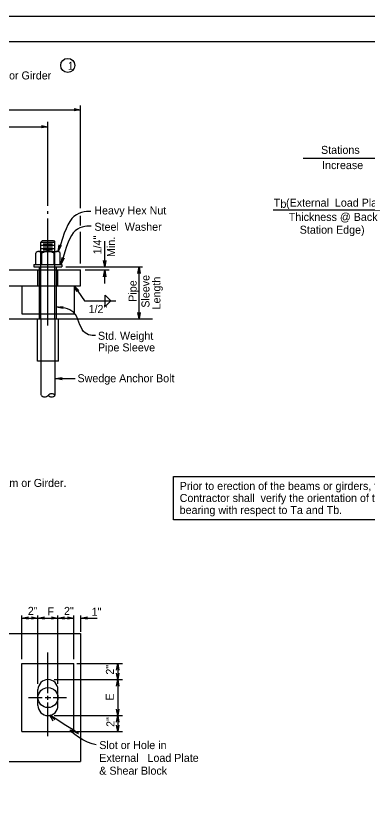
# Model space of a CAD drawing. Extents: x 113 to 232, y -103 to -27.
# Drawn here: x 181.6 to 185.26, y -54.65 to -46.32 of the extents above; entities that cross this region are included whole.
import ezdxf

# ---------------------------------------------------------------- set-up
doc = ezdxf.new("R2010")
doc.units = 0
for name, color, linetype in [('1', 7, 'Continuous'), ('B_Border', 7, 'Continuous'), ('B_Dimension', 7, 'Continuous'), ('B_No_Plot', 7, 'Continuous')]:
    doc.layers.add(name, color=color, linetype=linetype)

msp = doc.modelspace()

# ---------------------------------------------------------------- linework, layer by layer
at = {"layer": '1'}
for p, q in [((182.2718, -48.3172), (182.2718, -47.2475)), ((179.1359, -47.2922), (182.2718, -47.2922)), ((181.9318, -48.2933), (181.9318, -47.419)), ((180.706, -47.469), (181.9318, -47.469)), ((184.5891, -47.7957), (185.647, -47.7957)), ((181.9318, -48.3756), (181.9318, -48.3482)), ((184.2742, -48.333), (185.6721, -48.333)), ((181.9318, -49.5368), (181.9318, -48.4227)), ((182.2718, -48.4956), (182.2718, -48.3959)), ((182.2718, -48.8924), (182.2718, -48.5639)), ((181.8589, -48.6707), (181.8752, -48.6543)), ((181.8589, -48.6707), (182.0047, -48.6707)), ((181.8589, -48.7678), (181.8589, -48.6707)), ((181.8589, -48.6707), (182.0047, -48.6707)), ((181.8752, -48.6543), (181.9884, -48.6543)), ((181.8832, -48.687), (181.9804, -48.687)), ((181.9884, -48.6543), (182.0047, -48.6707)), ((182.0047, -48.7678), (182.0047, -48.6707)), ((182.5231, -48.9288), (182.5231, -48.6599)), ((181.8365, -48.7678), (182.0273, -48.7678)), ((181.8589, -48.7031), (182.0047, -48.7031)), ((181.8589, -48.7354), (182.0047, -48.7354)), ((181.8589, -49.4703), (181.8589, -48.7678)), ((181.8832, -48.7194), (181.9804, -48.7194)), ((181.8832, -48.7518), (181.9804, -48.7518)), ((182.0047, -49.4703), (182.0047, -48.7678)), ((181.8045, -48.9017), (181.8045, -48.7862)), ((181.8688, -48.9017), (181.8688, -48.7862)), ((181.995, -48.9017), (181.995, -48.7862)), ((182.0595, -48.9017), (182.0595, -48.7862)), ((181.786, -48.9017), (182.0776, -48.9017)), ((181.786, -48.9017), (181.786, -48.9277)), ((181.786, -48.9277), (182.0776, -48.9277)), ((181.8433, -48.9606), (181.8433, -48.9273)), ((182.0203, -48.9606), (182.0203, -48.9283)), ((182.0776, -48.9017), (182.0776, -48.9277)), ((182.1175, -48.9277), (182.9164, -48.9277)), ((182.8804, -49.4703), (182.8804, -48.9277)), ((179.1359, -48.9598), (182.2718, -48.9598)), ((181.8277, -49.1273), (181.8277, -48.9606)), ((181.8433, -49.1273), (181.8433, -48.9606)), ((182.0203, -49.1283), (182.0203, -48.9636)), ((182.0359, -49.1283), (182.0359, -48.9636)), ((182.2718, -49.1264), (182.2718, -48.9598)), ((182.3196, -48.9598), (182.5687, -48.9598)), ((182.5231, -49.0998), (182.5231, -48.9622)), ((179.1359, -49.1264), (182.2718, -49.1264)), ((181.661, -49.1264), (181.661, -49.4181)), ((181.8433, -49.4181), (181.8433, -49.1273)), ((182.0203, -49.4181), (182.0203, -49.1283)), ((182.2026, -49.1264), (182.2026, -49.4181)), ((182.2026, -49.1264), (182.3126, -49.2823)), ((182.5267, -49.3413), (182.5267, -49.2233)), ((182.5267, -49.2233), (182.5857, -49.2823)), ((182.3126, -49.2823), (182.639, -49.2823)), ((182.5857, -49.2823), (182.5267, -49.3413)), ((181.661, -49.4181), (182.2027, -49.4181)), ((181.8433, -49.4703), (181.8433, -49.4181)), ((182.0203, -49.4703), (182.0203, -49.4181)), ((178.3401, -49.4703), (183.0184, -49.4703)), ((181.8233, -49.9105), (181.8233, -49.4703)), ((181.8589, -49.4703), (181.8589, -49.9105)), ((182.0047, -49.4703), (182.0047, -49.9105)), ((182.0403, -49.9105), (182.0403, -49.4703)), ((182.0403, -49.9105), (181.8233, -49.9105)), ((181.8589, -49.9105), (181.8589, -50.2636)), ((182.0047, -49.9105), (182.0047, -50.2638)), ((182.0116, -50.0903), (182.2143, -50.0903)), ((181.6609, -53.011), (181.6609, -52.5571)), ((181.6609, -52.5832), (181.8276, -52.5832)), ((181.8276, -53.2697), (181.8276, -52.5571)), ((181.8276, -52.5832), (182.0359, -52.5832)), ((182.0359, -53.2697), (182.0359, -52.5571)), ((182.0359, -52.5832), (182.2025, -52.5832)), ((182.2025, -53.011), (182.2025, -52.5571)), ((182.2735, -52.7253), (182.2735, -52.5571)), ((182.2735, -52.5832), (182.4434, -52.5832)), ((181.3298, -52.7449), (182.2718, -52.7449)), ((182.2718, -52.7449), (182.2718, -54.0782)), ((181.9317, -53.3636), (181.9317, -52.9409)), ((181.6609, -53.0574), (182.2025, -53.0574)), ((181.6609, -53.7658), (181.6609, -53.0574)), ((182.2025, -53.7658), (182.2025, -53.0574)), ((182.2332, -53.0574), (182.709, -53.0574)), ((182.6581, -53.0574), (182.6581, -53.2241)), ((181.9955, -53.2241), (182.709, -53.2241)), ((182.6581, -53.2241), (182.6581, -53.5991)), ((181.8276, -53.4949), (181.8276, -53.3282)), ((182.0359, -53.4949), (182.0359, -53.3282)), ((181.728, -53.4116), (181.8722, -53.4116)), ((181.9034, -53.4116), (181.9626, -53.4116)), ((181.9317, -53.4331), (181.9317, -53.3914)), ((181.9869, -53.4116), (182.0359, -53.4116)), ((182.0359, -53.4116), (182.1258, -53.4116)), ((181.9317, -53.8125), (181.9317, -53.4626)), ((181.9955, -53.5991), (182.709, -53.5991)), ((182.6581, -53.5991), (182.6581, -53.7658)), ((181.6609, -53.7658), (182.2025, -53.7658)), ((182.2332, -53.7658), (182.709, -53.7658)), ((181.3263, -54.0782), (182.2718, -54.0782))]:
    msp.add_line(p, q, dxfattribs=at)
for points in [[(181.8252, -48.9598), (181.8252, -48.9598)], [(182.2322, -49.1893), (182.2026, -49.1264), (182.2518, -49.1753)]]:
    msp.add_lwpolyline(points, dxfattribs=at)
msp.add_lwpolyline([(183.2378, -51.111), (186.1787, -51.111), (186.1787, -51.5619), (183.2378, -51.5619)], close=True, dxfattribs=at)
for centre, radius in [((182.1373, -46.8307), 0.0733), ((181.9318, -53.4116), 0.1042)]:
    msp.add_circle(centre, radius, dxfattribs=at)
for centre, radius, start, end in [((181.8366, -48.8053), 0.0375, 30.80861, 149.1914), ((181.9319, -48.8859), 0.118, 57.68982, 122.31018), ((182.0273, -48.8055), 0.0376, 30.95728, 149.04272), ((181.8969, -50.2305), 0.0504, 223.71346, 316.28654), ((181.9698, -50.3002), 0.0504, 43.71346, 136.28654), ((181.9698, -50.2305), 0.0504, 223.71346, 316.28654), ((181.9318, -53.3282), 0.1042, 0, 180), ((181.9318, -53.4949), 0.1042, 180, 0)]:
    msp.add_arc(centre, radius, start, end, dxfattribs=at)
for points in [[(182.3767, -48.3506), (182.36, -48.35), (182.1729, -48.347), (182.102, -48.5671), (182.0375, -48.7678)], [(182.3799, -48.5045), (182.3635, -48.5039), (182.1862, -48.4973), (182.1251, -48.7063), (182.0707, -48.898)], [(182.4272, -49.6424), (182.4104, -49.6436), (182.2728, -49.6497), (182.2378, -49.3572), (182.0673, -49.3499), (182.0221, -49.3479)], [(182.4347, -53.9018), (182.3268, -53.8988), (181.9515, -53.5952), (182.4347, -53.9018), (181.9515, -53.5952)]]:
    msp.add_open_spline(points, degree=3, dxfattribs=at)
at = {"layer": 'B_Border'}
msp.add_line((177.6403, -46.5803), (198.7169, -46.5803), dxfattribs=at)
at = {"layer": 'B_Dimension'}
for points in [[(182.2035, -47.2802), (182.2718, -47.2922), (182.2035, -47.3043)], [(181.8635, -47.4569), (181.9318, -47.469), (181.8635, -47.481)], [(182.0699, -48.7065), (182.0375, -48.7678), (182.0469, -48.6991)], [(182.1009, -48.8355), (182.0707, -48.898), (182.0778, -48.829)], [(182.5352, -48.8605), (182.5231, -48.9288), (182.5111, -48.8605)], [(182.8684, -48.996), (182.8804, -48.9277), (182.8924, -48.996)], [(182.5111, -49.0305), (182.5231, -48.9622), (182.5352, -49.0305)], [(182.0899, -49.3629), (182.0221, -49.3479), (182.0909, -49.3388)], [(182.8924, -49.4019), (182.8804, -49.4703), (182.8684, -49.4019)], [(182.0799, -50.1023), (182.0116, -50.0903), (182.0799, -50.0782)], [(181.7292, -52.5953), (181.6609, -52.5832), (181.7292, -52.5712)], [(181.7592, -52.5712), (181.8276, -52.5832), (181.7592, -52.5953)], [(181.7592, -52.5712), (181.8276, -52.5832), (181.7592, -52.5953)], [(181.7592, -52.5712), (181.8276, -52.5832), (181.7592, -52.5953)], [(181.8959, -52.5953), (181.8276, -52.5832), (181.8959, -52.5712)], [(181.9676, -52.5712), (182.0359, -52.5832), (181.9676, -52.5953)], [(182.1042, -52.5953), (182.0359, -52.5832), (182.1042, -52.5712)], [(182.1342, -52.5712), (182.2025, -52.5832), (182.1342, -52.5953)], [(182.3418, -52.5953), (182.2735, -52.5832), (182.3418, -52.5712)], [(182.646, -53.1257), (182.6581, -53.0574), (182.6701, -53.1257)], [(182.6701, -53.1557), (182.6581, -53.2241), (182.646, -53.1557)], [(182.646, -53.2924), (182.6581, -53.2241), (182.6701, -53.2924)], [(181.9843, -53.6564), (181.9515, -53.5952), (182.0032, -53.6415)], [(182.6701, -53.5307), (182.6581, -53.5991), (182.646, -53.5307)], [(182.646, -53.6674), (182.6581, -53.5991), (182.6701, -53.6674)], [(182.6701, -53.6974), (182.6581, -53.7658), (182.646, -53.6974)]]:
    msp.add_lwpolyline(points, dxfattribs=at)
at = {"layer": 'B_No_Plot'}
msp.add_lwpolyline([(176.6886, -46.3166), (199.0219, -46.3166), (199.0219, -60.5406), (176.6886, -60.5406)], close=True, dxfattribs=at)

# ---------------------------------------------------------------- texts
at = {"layer": '1'}
for s, height, p in [('1', 0.0833, (182.1381, -46.8763)), ('C.L. Beam or Girder', 0.083334, (180.969, -46.9769)), ('Stations', 0.08333, (184.7738, -47.7518)), ('Increase', 0.08333, (184.7853, -47.9102)), ('T  (External  Load Plate', 0.083334, (184.2803, -48.3012)), ('b', 0.0833, (184.3512, -48.3133)), ('Heavy Hex Nut', 0.083334, (182.4138, -48.3821)), ('Thickness @ Back', 0.083334, (184.4378, -48.4496)), ('Steel  Washer', 0.083334, (182.4154, -48.5521)), ('Station Edge)', 0.083334, (184.5521, -48.5829)), ('1/2"', 0.08333, (182.3546, -49.4084)), ('Std. Weight ', 0.083334, (182.452, -49.6869)), ('Pipe Sleeve', 0.083334, (182.452, -49.8078)), ('Swedge Anchor Bolt', 0.083334, (182.2389, -50.1289)), ('C.L Elastomeric Pad shal l  be aligned with C.L. Beam or Girder.', 0.083334, (178.9532, -51.2186)), ('Prior to erection of the beams or girders, the ', 0.083334, (183.3027, -51.2501)), ('Contractor shall  verify the orientation of the ', 0.083334, (183.3027, -51.3751)), ('bearing with respect to Ta and Tb.', 0.083334, (183.3027, -51.5001)), ('2"', 0.08333, (181.722, -52.5506)), ('F', 0.0833, (181.9264, -52.5561)), ('2"', 0.08333, (182.0987, -52.5506)), ('1"', 0.08333, (182.3865, -52.5595)), ('Slot or Hole in', 0.083334, (182.4658, -53.9473)), ('External   Load Plate ', 0.083334, (182.4658, -54.0806)), ('& Shear Block', 0.083334, (182.4658, -54.2139))]:
    msp.add_text(s, height=height, dxfattribs=at).set_placement(p)
for s, height, p in [("1/4''", 0.08333, (182.4877, -48.7982)), ('Min.', 0.08333, (182.6301, -48.8252)), ('Sleeve ', 0.08333, (182.9883, -49.3529)), ('Pipe', 0.08333, (182.8544, -49.2908)), ('Length', 0.08333, (183.1022, -49.3706)), ('2"', 0.08333, (182.6179, -53.1726)), ('E', 0.0833, (182.6164, -53.4429)), ('2"', 0.08333, (182.6233, -53.7164))]:
    msp.add_text(s, height=height, rotation=90, dxfattribs=at).set_placement(p)

doc.saveas('drawing.dxf')
